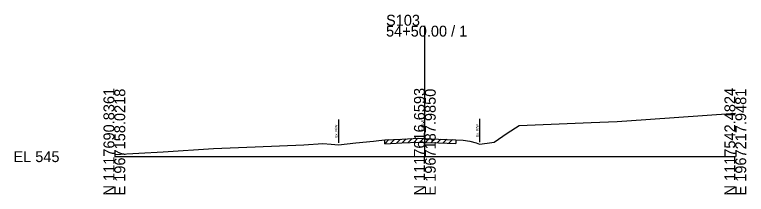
# Model space of a CAD drawing. Extents: x -26 to 163, y -10 to 24018.
# Drawn here: x -25.7 to 162.8, y 3990.3 to 4036.5 of the extents above; entities that cross this region are included whole.
import ezdxf

# ---------------------------------------------------------------- set-up
doc = ezdxf.new("R2010")
doc.units = 0
for name, color, linetype in [('RD_GPK_XS_Cell', 7, 'Continuous'), ('RD_XS_ExGround', 7, 'Continuous'), ('RD_XS_ExPaveRet', 7, 'Continuous'), ('RD_XS_ExRW', 7, 'Continuous'), ('RD_XS_TX_Elev_EX', 7, 'Continuous')]:
    doc.layers.add(name, color=color, linetype=linetype)

msp = doc.modelspace()

# ---------------------------------------------------------------- linework, layer by layer
at = {"layer": 'RD_GPK_XS_Cell'}
for p, q in [((80, 4000), (80, 4033.69)), ((0, 4000), (80, 4000)), ((80, 4000), (160, 4000))]:
    msp.add_line(p, q, dxfattribs=at)
at = {"layer": 'RD_XS_ExGround'}
msp.add_lwpolyline([(0, 4000.59), (12.58, 4001.24), (25.56, 4002.06), (36.29, 4002.55), (48.82, 4003.01), (53.73, 4003.35), (55.89, 4003.2), (57.73, 4003.08), (62.22, 4003.57), (66.79, 4004.02), (68.18, 4004.17), (69.67, 4004.33), (74.05, 4004.53), (78.48, 4004.73), (80, 4004.67), (83.51, 4004.54), (87.99, 4004.37), (89.83, 4004.2), (91.63, 4004.01), (93.23, 4003.58), (94.09, 4003.21), (96.08, 4003.5), (97.9, 4003.76), (101.23, 4006.06), (104.29, 4008.03), (122.85, 4008.79), (129.57, 4009.07), (136.95, 4009.58), (160, 4011.23)], dxfattribs=at)
at = {"layer": 'RD_XS_ExPaveRet'}
for p, q in [((71.17, 4003.4), (72.22, 4004.45)), ((72.67, 4003.47), (73.72, 4004.51)), ((74.17, 4003.53), (75.22, 4004.58)), ((75.67, 4003.6), (76.72, 4004.65)), ((77.17, 4003.67), (78.22, 4004.72)), ((78.67, 4003.72), (79.63, 4004.68)), ((80.17, 4003.67), (81.13, 4004.63)), ((81.67, 4003.61), (82.63, 4004.57)), ((83.17, 4003.55), (84.13, 4004.52)), ((84.67, 4003.5), (85.63, 4004.46)), ((69.67, 4003.33), (70.72, 4004.38)), ((69.67, 4003.33), (69.67, 4004.33)), ((69.67, 4003.33), (74.05, 4003.53)), ((74.05, 4003.53), (78.48, 4003.73)), ((78.48, 4003.73), (80, 4003.67)), ((80, 4003.67), (83.51, 4003.54)), ((83.51, 4003.54), (87.99, 4003.37)), ((86.17, 4003.44), (87.13, 4004.4)), ((87.99, 4004.37), (87.99, 4003.37))]:
    msp.add_line(p, q, dxfattribs=at)
at = {"layer": 'RD_XS_ExRW'}
for p, q in [((57.73, 4009.58), (57.73, 4003.58)), ((94.09, 4009.71), (94.09, 4003.71))]:
    msp.add_line(p, q, dxfattribs=at)

# ---------------------------------------------------------------- texts
at = {"layer": 'RD_GPK_XS_Cell'}
for s, p in [('S103', (70, 4033.69)), ('54+50.00 / 1', (70, 4030.89)), ('EL 545', (-26, 3998.6))]:
    msp.add_text(s, height=2.8, dxfattribs=at).set_placement(p)
for s, p in [('N 1117690.8361', (0, 3990)), ('E 1967158.0218', (2.8, 3990)), ('N 1117616.6593', (80, 3990)), ('E 1967187.9850', (82.8, 3990)), ('N 1117542.4824', (160, 3990)), ('E 1967217.9481', (162.8, 3990))]:
    msp.add_text(s, height=2.8, rotation=90, dxfattribs=at).set_placement(p)
at = {"layer": 'RD_XS_ExRW'}
for p in [(93.84, 4005.05), (57.48, 4004.92)]:
    msp.add_text('Ex. R/W ', height=0.65, rotation=90, dxfattribs=at).set_placement(p)
at = {"layer": 'RD_XS_TX_Elev_EX'}
msp.add_text('549.67', height=0.8, rotation=90, dxfattribs=at).set_placement((79.9, 4006.67))

doc.saveas('drawing.dxf')
